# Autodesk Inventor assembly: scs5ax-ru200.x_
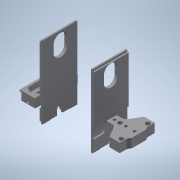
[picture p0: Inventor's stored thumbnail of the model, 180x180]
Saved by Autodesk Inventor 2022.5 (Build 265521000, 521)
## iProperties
Part Number: scs5ax-ru200.x_
Material: 一般
Document SubType Name: Assembly
Designer: ImaoCorp
Sending System: SOLIDWORKS 2017-2017317
MC: AMD64
MC_MODEL: Intel64 Family 6 Model 60 Stepping 3, GenuineIntel
OS: Windows_NT
FRU: Parasolid Version 29.0, build 201,  4-17-2017
FORMAT: text
GUISE: transmit
KEY: scs5ax-ru200
FILE: scs5ax-ru200.x_t
DATE: Wed Sep 18 16:18:35 2019
Author: ImaoCorp
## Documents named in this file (5)
- X:\14_SW2022-Inv2022\00_全2023-1023新製品(TCC)まで\s\scs5ax-ru200\SCS5AX-RU200.iam
- X:\14_SW2022-Inv2022\00_全2023-1023新製品(TCC)まで\s\scs5ax-ru200\scs5ax-ru200_01.ipt
- X:\14_SW2022-Inv2022\00_全2023-1023新製品(TCC)まで\s\scs5ax-ru200\scs5ax-ru200_02.ipt
- X:\14_SW2022-Inv2022\00_全2023-1023新製品(TCC)まで\s\scs5ax-ru200\scs5ax-ru200_03.ipt
- X:\14_SW2022-Inv2022\00_全2023-1023新製品(TCC)まで\s\scs5ax-ru200\scs5ax-ru200_04.ipt
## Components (4 placed, 4 different names)
1. scs5ax-ru200_01
2. scs5ax-ru200_02
3. scs5ax-ru200_03
4. scs5ax-ru200_04
